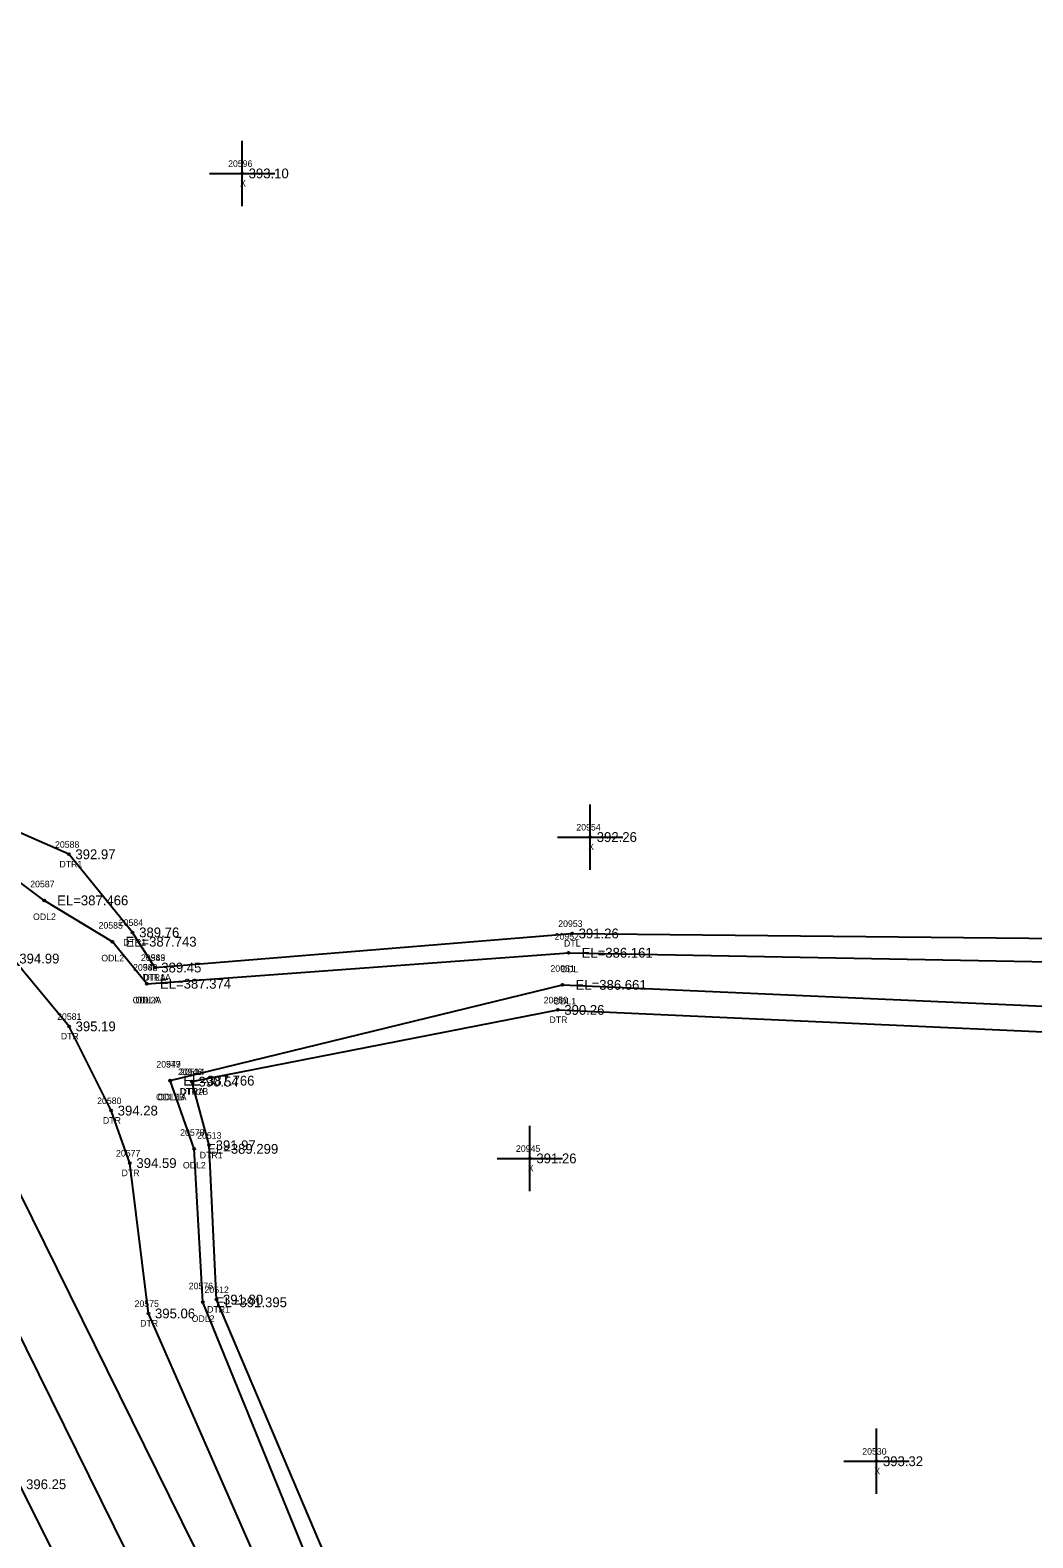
# Model space of a CAD drawing. Extents: x 2186623 to 2187804, y 1079975 to 1082766.
# Drawn here: x 2187050.6 to 2187203.9, y 1082125.2 to 1082355.8 of the extents above; entities that cross this region are included whole.
import ezdxf

# ---------------------------------------------------------------- set-up
doc = ezdxf.new("R2010")
doc.units = 0
for name, color, linetype in [('RD_DTM_BkLn1', 7, 'Continuous'), ('RD_EX_H2O', 7, 'Continuous'), ('RD_EX_H2O_txCode', 7, 'Continuous'), ('RD_EX_Misc', 7, 'Continuous'), ('RD_EX_Misc_txCode', 7, 'Continuous'), ('RD_EX_Road', 7, 'Continuous'), ('RD_EX_TX_Driveway_ELEV', 7, 'Continuous'), ('RD_EX_TX_H2O_ELEV', 7, 'Continuous'), ('RD_EX_TX_Misc_ELEV', 7, 'Continuous'), ('RD_EX_TX_Road_ELEV', 7, 'Continuous'), ('RD_SMD_Locator', 7, 'Continuous')]:
    doc.layers.add(name, color=color, linetype=linetype)

msp = doc.modelspace()

# ---------------------------------------------------------------- linework, layer by layer
at = {"layer": 'RD_DTM_BkLn1'}
msp.add_lwpolyline([(2187423.87, 1081398.18), (2187387.08, 1081472.03), (2187341.23, 1081563.21), (2187295.24, 1081657.28), (2187251.34, 1081744.68), (2187208.12, 1081834.1), (2187164.51, 1081922.08), (2187120.25, 1082011.57), (2187076.78, 1082099.89), (2187032.8, 1082188.99), (2186987.81, 1082278.27), (2186943.85, 1082367.59), (2186899.96, 1082456.58), (2186856.34, 1082544.86), (2186810.78, 1082636.89), (2186773.78, 1082711.06)], dxfattribs=at)
at = {"layer": 'RD_EX_H2O'}
for points in [[(2187194.42, 1081921.93), (2187188.23, 1081917.94), (2187181.17, 1081931.31), (2187136.64, 1082019.21), (2187091.33, 1082107.81), (2187068.66, 1082159.56), (2187065.82, 1082182.56), (2187062.96, 1082190.59), (2187056.52, 1082203.47), (2187047.91, 1082213.84), (2187030.41, 1082231.92), (2187001.98, 1082284.32), (2186967.42, 1082359.95), (2186975.57, 1082384.17), (2187023.93, 1082440.63)], [(2187068.42, 1082209.99), (2187063.14, 1082216.42), (2187052.7, 1082222.74), (2187036.02, 1082235.21), (2187010.3, 1082288.66), (2186989.67, 1082337.91), (2186975, 1082362.36), (2186975.7, 1082367.63), (2186978.06, 1082371.76), (2187025.68, 1082438.74)], [(2187069.62, 1082212.47), (2187066.24, 1082217.84), (2187056.49, 1082229.79), (2187039.47, 1082237.24), (2187012.75, 1082290.32), (2186993.91, 1082339.72), (2186981.02, 1082367.99), (2187027.6, 1082436.93)], [(2187069.62, 1082212.47), (2187133.44, 1082217.68), (2187248.19, 1082216.51), (2187273.3, 1082211.99), (2187338.22, 1082209.8), (2187358.72, 1082219.76), (2187404.26, 1082207.51), (2187466.25, 1082202.07), (2187557.26, 1082201.78)], [(2187068.42, 1082209.99), (2187132.89, 1082214.73), (2187247.38, 1082212.6), (2187273, 1082207), (2187337.94, 1082206.81), (2187358.1, 1082212.78), (2187403.78, 1082202.53), (2187465.56, 1082198.13), (2187556.99, 1082197.63)], [(2187071.99, 1082195.17), (2187131.97, 1082209.82), (2187245.75, 1082204.76), (2187272.7, 1082202.01), (2187337.48, 1082201.83), (2187357.57, 1082206.81), (2187403.29, 1082197.55), (2187464.35, 1082191.23), (2187554.91, 1082189.91)], [(2187075.31, 1082195.02), (2187131.25, 1082205.99), (2187244.94, 1082200.85), (2187272.46, 1082198.02), (2187337.02, 1082196.86), (2187357.31, 1082203.82), (2187402.91, 1082193.57), (2187463.83, 1082188.28), (2187553.34, 1082184.11)], [(2187191.11, 1081921.63), (2187185.32, 1081933.71), (2187141, 1082021.49), (2187097.45, 1082111.02), (2187076.96, 1082161.27), (2187075.63, 1082184.74), (2187071.99, 1082195.17)], [(2187194.42, 1081921.93), (2187186.68, 1081934.37), (2187143.07, 1082022.34), (2187100.33, 1082111.64), (2187079.06, 1082161.68), (2187077.93, 1082185.29), (2187075.31, 1082195.02)]]:
    msp.add_lwpolyline(points, dxfattribs=at)
at = {"layer": 'RD_EX_Misc'}
for p, q in [((2187082.98, 1082328.93), (2187082.98, 1082338.93)), ((2187077.98, 1082333.93), (2187087.98, 1082333.93)), ((2187136.21, 1082227.43), (2187136.21, 1082237.43)), ((2187131.21, 1082232.43), (2187141.21, 1082232.43)), ((2187126.98, 1082178.28), (2187126.98, 1082188.28)), ((2187121.98, 1082183.28), (2187131.98, 1082183.28)), ((2187179.97, 1082131.96), (2187179.97, 1082141.96)), ((2187174.97, 1082136.96), (2187184.97, 1082136.96))]:
    msp.add_line(p, q, dxfattribs=at)
at = {"layer": 'RD_EX_Road'}
for points in [[(2187433.48, 1081402.93), (2187431.23, 1081405.14), (2187428.77, 1081409.96), (2187395.59, 1081476.3), (2187350.19, 1081567.64), (2187304.81, 1081661.14), (2187260.59, 1081749.11), (2187216.69, 1081837.7), (2187187.21, 1081897.62), (2187180.39, 1081911.5), (2187172.85, 1081926.68), (2187129.14, 1082015.5), (2187085.24, 1082104.53), (2187041.33, 1082193.41), (2186996.73, 1082282.37), (2186965.72, 1082345.62), (2186953.24, 1082372.4), (2186921.8, 1082435.38), (2186908.96, 1082460.32), (2186865.29, 1082548.82), (2186820.07, 1082641.92), (2186783.9, 1082716)], [(2187412.76, 1081392.41), (2187413.27, 1081397.3), (2187377.92, 1081468.69), (2187333.03, 1081559.63), (2187287.24, 1081651.83), (2187243.42, 1081739.85), (2187221.49, 1081785.01), (2187215.17, 1081798.71), (2187200.07, 1081829.29), (2187156, 1081917.87), (2187111.96, 1082007.49), (2187067.92, 1082095.45), (2187048.95, 1082133.44), (2187040.02, 1082149.93), (2187023.25, 1082184.23), (2186978.93, 1082274.21), (2186935.28, 1082363.16), (2186891.66, 1082452.64), (2186848.32, 1082541.12), (2186802.48, 1082632.77), (2186765.18, 1082707.62)]]:
    msp.add_lwpolyline(points, dxfattribs=at)
at = {"layer": 'RD_SMD_Locator'}
for centre in [(2187082.98, 1082333.93), (2187136.21, 1082232.43), (2187056.49, 1082229.79), (2187052.7, 1082222.74), (2187066.24, 1082217.84), (2187133.44, 1082217.68), (2187063.14, 1082216.42), (2187132.89, 1082214.73), (2187069.62, 1082212.47), (2187069.62, 1082212.47), (2187068.42, 1082209.99), (2187068.42, 1082209.99), (2187131.97, 1082209.82), (2187131.25, 1082205.99), (2187056.52, 1082203.47), (2187071.99, 1082195.17), (2187071.99, 1082195.17), (2187075.31, 1082195.02), (2187075.31, 1082195.02), (2187062.96, 1082190.59), (2187075.63, 1082184.74), (2187077.93, 1082185.29), (2187065.82, 1082182.56), (2187126.98, 1082183.28), (2187076.96, 1082161.27), (2187079.06, 1082161.68), (2187068.66, 1082159.56), (2187179.97, 1082136.96)]:
    msp.add_circle(centre, 0.15, dxfattribs=at)

# ---------------------------------------------------------------- texts
at = {"layer": 'RD_EX_H2O_txCode'}
for s, p in [('20588', (2187054.37, 1082230.79)), ('DTR1', (2187055.05, 1082227.79)), ('20587', (2187050.58, 1082224.74)), ('ODL2', (2187051.01, 1082219.74)), ('20585', (2187061.03, 1082218.42)), ('20584', (2187064.12, 1082218.84)), ('20953', (2187131.32, 1082218.68)), ('DTR1', (2187064.81, 1082215.84)), ('20952', (2187130.77, 1082216.73)), ('ODL2', (2187061.45, 1082213.42)), ('20583', (2187067.51, 1082213.47)), ('20949', (2187067.51, 1082213.47)), ('DTL', (2187132.2, 1082215.68)), ('20582', (2187066.31, 1082211.99)), ('20948', (2187066.31, 1082211.99)), ('20951', (2187130.13, 1082211.82)), ('ODL', (2187131.64, 1082211.73)), ('DTR1A', (2187067.7, 1082210.47)), ('DTLA', (2187067.89, 1082210.47)), ('ODL2A', (2187066.24, 1082206.99)), ('ODLA', (2187066.69, 1082206.99)), ('20950', (2187129.09, 1082206.99)), ('ODL1', (2187130.56, 1082206.82)), ('20581', (2187054.69, 1082204.47)), ('DTR', (2187129.98, 1082203.99)), ('DTR', (2187055.26, 1082201.47)), ('20579', (2187069.87, 1082197.17)), ('20947', (2187069.87, 1082197.17)), ('20946', (2187073.17, 1082196.02)), ('20514', (2187073.48, 1082196.02)), ('DTR1B', (2187073.41, 1082193.02)), ('DTRA', (2187073.56, 1082193.02)), ('20580', (2187060.81, 1082191.59)), ('ODL2B', (2187069.82, 1082192.17)), ('ODL1A', (2187070.09, 1082192.17)), ('DTR', (2187061.7, 1082188.59)), ('20578', (2187073.51, 1082186.74)), ('20513', (2187076.1, 1082186.29)), ('20577', (2187063.7, 1082183.56)), ('ODL2', (2187073.93, 1082181.74)), ('DTR1', (2187076.5, 1082183.29)), ('DTR', (2187064.55, 1082180.56)), ('20576', (2187074.82, 1082163.27)), ('20512', (2187077.23, 1082162.68)), ('20575', (2187066.54, 1082160.56)), ('ODL2', (2187075.27, 1082158.27)), ('DTR1', (2187077.63, 1082159.68)), ('DTR', (2187067.39, 1082157.56))]:
    msp.add_text(s, height=1, dxfattribs=at).set_placement(p)
at = {"layer": 'RD_EX_Misc_txCode'}
for s, p in [('20596', (2187080.84, 1082334.93)), ('X', (2187082.67, 1082331.93)), ('20954', (2187134.09, 1082233.43)), ('X', (2187135.9, 1082230.43)), ('20945', (2187124.86, 1082184.28)), ('X', (2187126.67, 1082181.28)), ('20530', (2187177.81, 1082137.96)), ('X', (2187179.66, 1082134.96))]:
    msp.add_text(s, height=1, dxfattribs=at).set_placement(p)
at = {"layer": 'RD_EX_TX_Driveway_ELEV'}
msp.add_text('396.25', height=1.5, dxfattribs=at).set_placement((2187049.95, 1082132.69))
at = {"layer": 'RD_EX_TX_H2O_ELEV'}
for s, p in [('392.97', (2187057.49, 1082229.04)), ('EL=387.466', (2187054.7, 1082221.99)), ('EL=387.743', (2187065.14, 1082215.67)), ('389.76', (2187067.24, 1082217.09)), ('391.26', (2187134.44, 1082216.93)), ('394.99', (2187048.91, 1082213.09)), ('EL=386.161', (2187134.89, 1082213.98)), ('389.45', (2187070.62, 1082211.72)), ('389.45', (2187070.62, 1082211.72)), ('EL=387.374', (2187070.42, 1082209.24)), ('EL=387.374', (2187070.42, 1082209.24)), ('EL=386.661', (2187133.97, 1082209.07)), ('390.26', (2187132.25, 1082205.24)), ('395.19', (2187057.52, 1082202.72)), ('EL=387.766', (2187073.99, 1082194.42)), ('EL=387.766', (2187073.99, 1082194.42)), ('390.54', (2187076.31, 1082194.27)), ('390.54', (2187076.31, 1082194.27)), ('394.28', (2187063.96, 1082189.84)), ('EL=389.299', (2187077.63, 1082183.99)), ('391.97', (2187078.93, 1082184.54)), ('394.59', (2187066.82, 1082181.81)), ('EL=391.395', (2187078.96, 1082160.52)), ('391.80', (2187080.06, 1082160.93)), ('395.06', (2187069.66, 1082158.81))]:
    msp.add_text(s, height=1.5, dxfattribs=at).set_placement(p)
at = {"layer": 'RD_EX_TX_Misc_ELEV'}
for s, p in [('393.10', (2187083.98, 1082333.18)), ('392.26', (2187137.21, 1082231.68)), ('391.26', (2187127.98, 1082182.53)), ('393.32', (2187180.97, 1082136.21))]:
    msp.add_text(s, height=1.5, dxfattribs=at).set_placement(p)
at = {"layer": 'RD_EX_TX_Road_ELEV'}
msp.add_text('396.25', height=1.5, dxfattribs=at).set_placement((2187049.95, 1082132.69))

doc.saveas('drawing.dxf')
